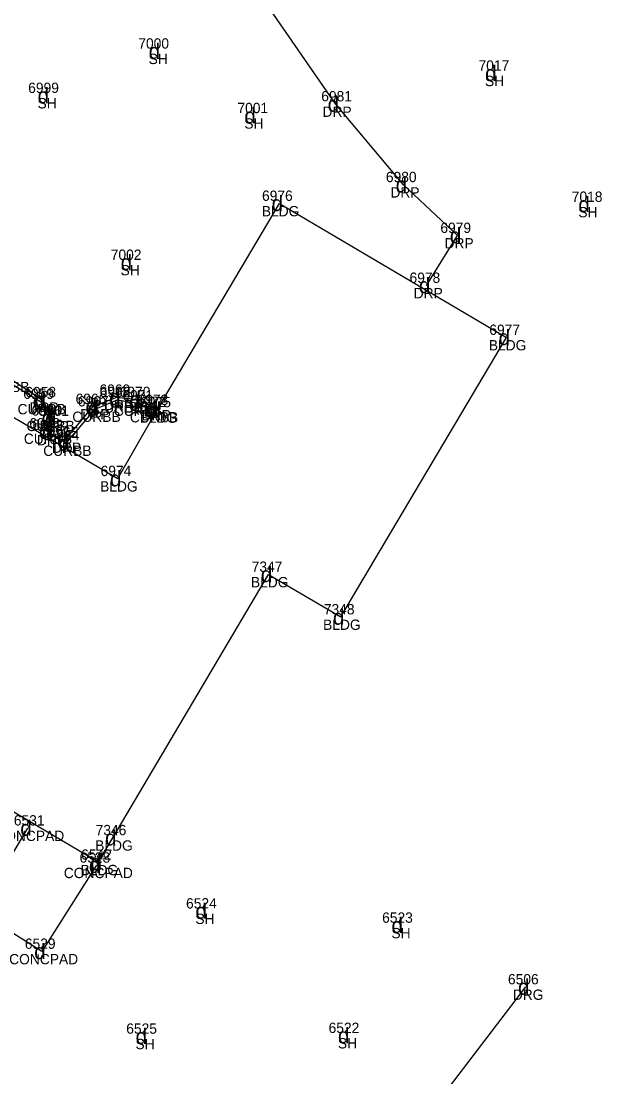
# Model space of a CAD drawing. Extents: x 69415 to 80913, y 7576 to 15059.
# Drawn here: x 75900.1 to 76012.6, y 14387.3 to 14592 of the extents above; entities that cross this region are included whole.
import ezdxf

# ---------------------------------------------------------------- set-up
doc = ezdxf.new("R2010")
doc.units = 0
for name, color, linetype in [('Level 11', 7, 'Continuous'), ('Level 12', 7, 'Continuous'), ('Level 13', 7, 'Continuous'), ('Level 46', 7, 'Continuous'), ('Level 47', 7, 'Continuous')]:
    doc.layers.add(name, color=color, linetype=linetype)

msp = doc.modelspace()

# ---------------------------------------------------------------- linework, layer by layer
at = {"layer": 'Level 11'}
for p, q in [((75960.96, 14575.9), (75947.2, 14595.8)), ((75974.13, 14560.24), (75960.96, 14575.9)), ((75984.62, 14550.39), (75974.13, 14560.24)), ((75978.63, 14540.71), (75984.62, 14550.39)), ((75897.07, 14523.19), (75904.19, 14518.54)), ((75896.73, 14522.52), (75903.8, 14518.22)), ((75903.8, 14518.22), (75905.51, 14514.97)), ((75904.19, 14518.54), (75906.17, 14514.92)), ((75908.56, 14510.74), (75914.03, 14517.23)), ((75914.03, 14517.23), (75918.62, 14519.02)), ((75914.41, 14516.75), (75918.65, 14518.54)), ((75918.62, 14519.02), (75922.56, 14518.57)), ((75918.65, 14518.54), (75922.43, 14517.92)), ((75922.43, 14517.92), (75925.56, 14516.65)), ((75922.56, 14518.57), (75925.93, 14517.05)), ((75908.76, 14510.16), (75914.41, 14516.75)), ((75905.51, 14514.97), (75905, 14512.49)), ((75906.17, 14514.92), (75905.61, 14512.19)), ((75905, 14512.49), (75908.76, 14510.16)), ((75977.9, 14378.57), (75997.84, 14404.7))]:
    msp.add_line(p, q, dxfattribs=at)
at = {"layer": 'Level 12'}
for p, q in [((75891.7, 14419.32), (75901.39, 14435.5)), ((75914.69, 14428.3), (75904.09, 14411.59)), ((75904.09, 14411.59), (75891.7, 14419.32))]:
    msp.add_line(p, q, dxfattribs=at)
at = {"layer": 'Level 13'}
for p, q in [((75926.45, 14516.58), (75950.1, 14556.61)), ((75950.1, 14556.61), (75994.09, 14530.62)), ((75961.98, 14476.43), (75994.09, 14530.62)), ((75876.05, 14528.45), (75918.77, 14503.25)), ((75918.77, 14503.25), (75926.45, 14516.58)), ((75917.82, 14433.62), (75948, 14484.68)), ((75948, 14484.68), (75961.98, 14476.43)), ((75914.99, 14428.87), (75842.58, 14471.77)), ((75914.99, 14428.87), (75917.82, 14433.62))]:
    msp.add_line(p, q, dxfattribs=at)

# ---------------------------------------------------------------- texts
at = {"layer": 'Level 46'}
for s, p in [('7000', (75922.77, 14586.63)), ('SH', (75924.76, 14583.63)), ('7017', (75988.69, 14582.35)), ('SH', (75989.95, 14579.35)), ('6999', (75901.43, 14578.03)), ('6981', (75958.22, 14576.4)), ('SH', (75903.24, 14575.03)), ('7001', (75941.97, 14574.12)), ('DRP', (75958.45, 14573.4)), ('SH', (75943.31, 14571.12)), ('6980', (75970.74, 14560.74)), ('6976', (75946.74, 14557.11)), ('DRP', (75971.62, 14557.74)), ('7018', (76006.76, 14556.92)), ('BLDG', (75946.69, 14554.11)), ('SH', (76008.02, 14553.92)), ('6979', (75981.3, 14550.89)), ('DRP', (75982.1, 14547.89)), ('7002', (75917.43, 14545.67)), ('SH', (75919.33, 14542.67)), ('6978', (75975.32, 14541.21)), ('DRP', (75976.12, 14538.21)), ('6977', (75990.78, 14531.12)), ('BLDG', (75990.68, 14528.12)), ('CURBB', (75892.32, 14520.02)), ('6969', (75915.26, 14519.52)), ('6959', (75900.48, 14518.72)), ('6958', (75900.88, 14519.04)), ('6966', (75910.62, 14517.73)), ('6967', (75911.05, 14517.25)), ('6968', (75915.29, 14519.04)), ('6970', (75919.17, 14519.07)), ('6971', (75919.69, 14518.42)), ('6972', (75922.25, 14517.15)), ('6973', (75922.63, 14517.55)), ('6975', (75923.14, 14517.08)), ('CURBB', (75899.38, 14515.72)), ('DRP', (75901.67, 14516.04)), ('6960', (75902.07, 14515.47)), ('6961', (75903.38, 14515.42)), ('CURBB', (75914.23, 14516.04)), ('DRP', (75916.11, 14516.52)), ('CURBB', (75918.01, 14515.42)), ('DRP', (75920.05, 14516.07)), ('6963', (75901.65, 14512.99)), ('CURBB', (75909.99, 14514.25)), ('DRP', (75911.52, 14514.73)), ('CURBB', (75921.14, 14514.15)), ('BLDG', (75923.04, 14514.08)), ('DRP', (75923.42, 14514.55)), ('CURBB', (75901.09, 14512.47)), ('6962', (75902.26, 14512.69)), ('DRP', (75903.66, 14512.42)), ('6965', (75905.2, 14511.24)), ('CURBB', (75900.58, 14509.99)), ('DRP', (75903.1, 14509.69)), ('6964', (75905.4, 14510.66)), ('CURBB', (75904.34, 14507.66)), ('DRP', (75906.04, 14508.24)), ('6974', (75915.46, 14503.75)), ('BLDG', (75915.36, 14500.75)), ('7347', (75944.74, 14485.18)), ('BLDG', (75944.59, 14482.18)), ('7348', (75958.72, 14476.93)), ('BLDG', (75958.57, 14473.93)), ('6531', (75898.65, 14436)), ('7346', (75914.5, 14434.12)), ('CONCPAD', (75895.04, 14433)), ('BLDG', (75914.41, 14431.12)), ('6542', (75911.69, 14429.37)), ('6528', (75911.38, 14428.8)), ('CONCPAD', (75908.33, 14425.8)), ('BLDG', (75911.58, 14426.37)), ('6524', (75932.02, 14419.91)), ('SH', (75933.82, 14416.91)), ('6523', (75970.01, 14417.14)), ('SH', (75971.81, 14414.14)), ('6529', (75900.78, 14412.09)), ('CONCPAD', (75897.74, 14409.09)), ('6506', (75994.4, 14405.2)), ('DRG', (75995.33, 14402.2)), ('6525', (75920.43, 14395.63)), ('6522', (75959.64, 14395.78)), ('SH', (75922.22, 14392.63)), ('SH', (75961.44, 14392.78))]:
    msp.add_text(s, height=2, dxfattribs=at).set_placement(p)
at = {"layer": 'Level 47'}
for p in [(75924.78, 14584.63), (75989.96, 14580.35), (75903.25, 14576.03), (75959.46, 14574.4), (75943.32, 14572.12), (75972.63, 14558.74), (75948.6, 14555.11), (76008.03, 14554.92), (75983.12, 14548.89), (75919.34, 14543.67), (75977.13, 14539.21), (75992.59, 14529.12), (75902.3, 14516.72), (75902.69, 14517.04), (75917.12, 14517.52), (75917.15, 14517.04), (75920.93, 14516.42), (75921.06, 14517.07), (75912.53, 14515.73), (75912.91, 14515.25), (75924.06, 14515.15), (75924.43, 14515.55), (75924.95, 14515.08), (75904.01, 14513.47), (75904.67, 14513.42), (75903.5, 14510.99), (75904.11, 14510.69), (75907.06, 14509.24), (75907.26, 14508.66), (75917.27, 14501.75), (75946.5, 14483.18), (75960.48, 14474.93), (75899.89, 14434), (75916.32, 14432.12), (75913.19, 14426.8), (75913.49, 14427.37), (75933.83, 14417.91), (75971.82, 14415.14), (75902.59, 14410.09), (75996.34, 14403.2), (75922.24, 14393.63), (75961.45, 14393.78)]:
    msp.add_text('d', height=3, dxfattribs=at).set_placement(p)

doc.saveas('drawing.dxf')
